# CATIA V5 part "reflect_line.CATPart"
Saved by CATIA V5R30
Part number: Part1
Bounding box of the stored display mesh (mm): x -137.722 to 27.889, y -12.795 to 48.468, z 0 to 139
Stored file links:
  D:\PROJECTS\CATIA V56R 2020\Resources\Parts File\c17_catia_v6_6r2020_prt\reflect_line.CATPart
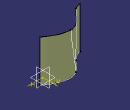
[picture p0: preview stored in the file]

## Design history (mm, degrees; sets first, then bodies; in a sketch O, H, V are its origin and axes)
Set1
  Sketch1 on xy-plane, origin (0, 0, 0), H (1, 0, 0), V (0, 1, 0)
    spline S1 through (27.8894, 17.3949) (-93.4438, 17.3949) (-113.5702, -2.4439) (-137.7218, -12.7946)
  Extrude1: Element1 Sketch1, Lim1 139, Lim2 0
  ReflectLine1: Support Extrude1, Direction (0, 0, 1), Angle 64, Origin vertex [face of Extrude1 from Sketch1.S1]
Body1 (main body)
